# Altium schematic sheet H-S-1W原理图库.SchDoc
size 127 x 99 mm
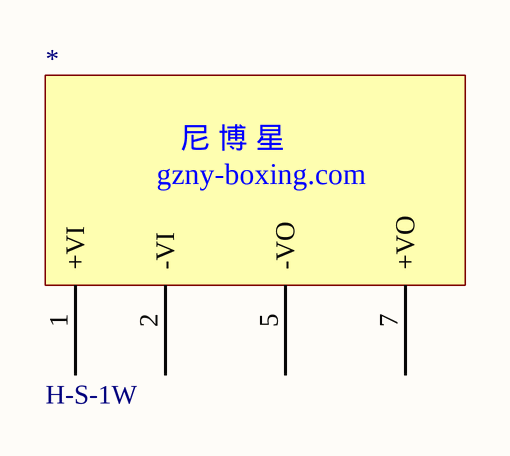
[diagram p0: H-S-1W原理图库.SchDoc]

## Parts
*  H-S-1W

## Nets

Not connected (* = marked no-connect by the designer): * 1(+VI) 2(-VI) 5(-VO) 7(+VO)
